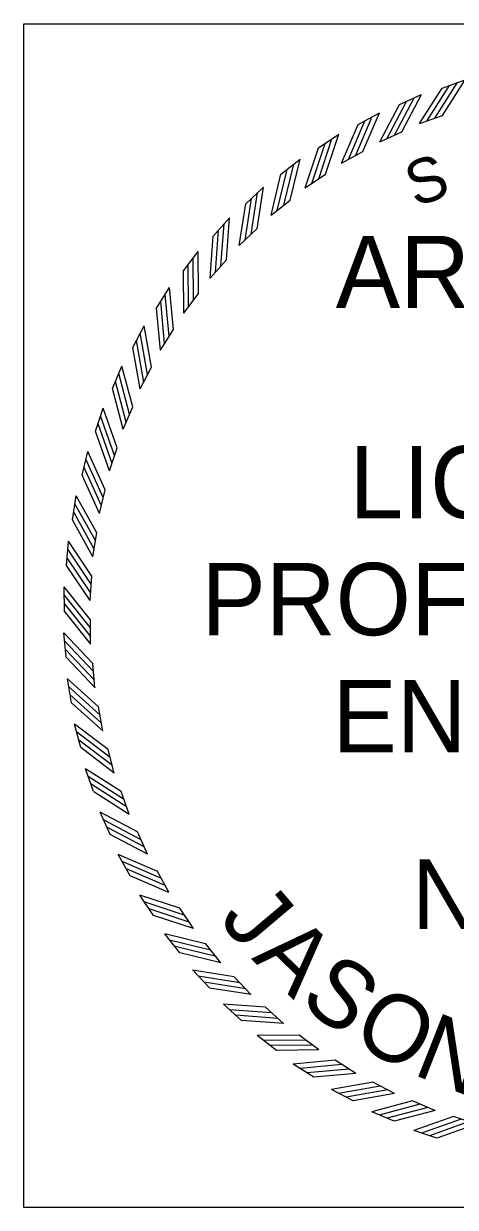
# Model space of a CAD drawing. Extents: x 0 to 1228740, y 0 to 152440.
# Drawn here: x 34.454 to 35.456, y 22.732 to 25.482 of the extents above; entities that cross this region are included whole.
import ezdxf

# ---------------------------------------------------------------- set-up
doc = ezdxf.new("R2010")
doc.units = 0
doc.layers.add('STAMP_JMT', color=7, linetype='Continuous')

msp = doc.modelspace()

# ---------------------------------------------------------------- linework, layer by layer
at = {"layer": 'STAMP_JMT'}
for p, q in [((35.4258, 25.332), (35.4792, 25.3509)), ((35.3263, 25.2938), (35.3779, 25.317)), ((35.2303, 25.2474), (35.2798, 25.2748)), ((35.3732, 25.2496), (35.4266, 25.2684)), ((35.1385, 25.1933), (35.1855, 25.2247)), ((35.2806, 25.2072), (35.3323, 25.2305)), ((35.0514, 25.1318), (35.0957, 25.167)), ((35.1919, 25.1574), (35.2415, 25.1849)), ((35.1077, 25.1005), (35.1548, 25.1319)), ((34.9697, 25.0634), (35.011, 25.1021)), ((35.0284, 25.0367), (35.0728, 25.072)), ((34.894, 24.9884), (34.9319, 25.0303)), ((34.9546, 24.9667), (34.9959, 25.0055)), ((34.8247, 24.9074), (34.859, 24.9523)), ((34.8869, 24.8908), (34.9249, 24.9328)), ((34.7623, 24.821), (34.7928, 24.8686)), ((34.8256, 24.8095), (34.86, 24.8546)), ((34.7072, 24.7297), (34.7337, 24.7796)), ((34.7713, 24.7235), (34.8019, 24.7712)), ((34.6599, 24.6341), (34.6822, 24.6861)), ((34.7243, 24.6333), (34.7508, 24.6834)), ((34.6207, 24.535), (34.6386, 24.5887)), ((34.6849, 24.5395), (34.7072, 24.5916)), ((34.5897, 24.433), (34.6031, 24.488)), ((34.6534, 24.4428), (34.6713, 24.4966)), ((34.63, 24.3438), (34.6434, 24.3989)), ((34.5673, 24.3288), (34.5761, 24.3847)), ((34.6148, 24.2432), (34.6236, 24.2992)), ((34.5536, 24.2231), (34.5578, 24.2795)), ((34.5487, 24.1166), (34.5481, 24.1732)), ((34.608, 24.1417), (34.6121, 24.1982)), ((34.6095, 24.04), (34.609, 24.0967)), ((34.5525, 24.0101), (34.5473, 24.0664)), ((34.6195, 23.9388), (34.6143, 23.9952)), ((34.5652, 23.9042), (34.5554, 23.9599)), ((34.6378, 23.8387), (34.628, 23.8945)), ((34.5865, 23.7998), (34.5721, 23.8545)), ((34.6643, 23.7405), (34.6499, 23.7953)), ((34.6164, 23.6975), (34.5976, 23.7508)), ((34.6989, 23.6448), (34.68, 23.6982)), ((34.6547, 23.598), (34.6315, 23.6495)), ((34.7412, 23.5523), (34.7179, 23.604)), ((34.701, 23.502), (34.6736, 23.5515)), ((34.791, 23.4636), (34.7636, 23.5132)), ((34.7551, 23.4101), (34.7237, 23.4572)), ((34.8479, 23.3793), (34.8165, 23.4264)), ((34.8166, 23.3231), (34.7814, 23.3674)), ((34.9117, 23.3), (34.8765, 23.3444)), ((34.8851, 23.2414), (34.8464, 23.2826)), ((34.9817, 23.2262), (34.943, 23.2676)), ((34.96, 23.1656), (34.9181, 23.2035)), ((35.0576, 23.1585), (35.0156, 23.1965)), ((35.041, 23.0963), (34.9961, 23.1306)), ((35.1389, 23.0973), (35.0938, 23.1317)), ((35.2249, 23.043), (35.1772, 23.0735)), ((35.1275, 23.0339), (35.0798, 23.0644)), ((35.3151, 22.996), (35.265, 23.0225)), ((35.2188, 22.9789), (35.1688, 23.0053)), ((35.4089, 22.9565), (35.3568, 22.9788)), ((35.3143, 22.9316), (35.2623, 22.9538)), ((35.5056, 22.925), (35.4518, 22.9429)), ((35.4134, 22.8923), (35.3597, 22.9102))]:
    msp.add_line(p, q, dxfattribs=at)
msp.add_lwpolyline([(34.454, 25.4817), (37.204, 25.4817), (37.204, 22.7317), (34.454, 22.7317)], close=True, dxfattribs=at)
for points in [[(35.3731, 25.2495), (35.4258, 25.3319)], [(35.3903, 25.2554), (35.443, 25.3378)], [(35.4087, 25.2623), (35.4614, 25.3448)], [(35.4265, 25.2685), (35.4792, 25.3509)], [(35.2973, 25.2145), (35.343, 25.301)], [(35.315, 25.2229), (35.3607, 25.3095)], [(35.3323, 25.2305), (35.3779, 25.317)], [(35.2415, 25.1849), (35.2798, 25.2749)], [(35.2806, 25.2072), (35.3263, 25.2937)], [(35.1919, 25.1574), (35.2303, 25.2474)], [(35.2079, 25.166), (35.2463, 25.256)], [(35.2249, 25.1759), (35.2633, 25.2659)], [(35.1547, 25.1319), (35.1856, 25.2248)], [(35.1076, 25.1004), (35.1385, 25.1933)], [(35.1229, 25.1103), (35.1537, 25.2032)], [(35.139, 25.1216), (35.1698, 25.2145)], [(35.0727, 25.072), (35.0957, 25.1671)], [(35.0427, 25.0478), (35.0658, 25.1429)], [(35.0578, 25.0604), (35.0809, 25.1555)], [(35.0283, 25.0367), (35.0514, 25.1318)], [(34.982, 24.9927), (34.9971, 25.0894)], [(34.9959, 25.0054), (35.011, 25.1021)], [(34.9546, 24.9666), (34.9697, 25.0633)], [(34.968, 24.9789), (34.9831, 25.0756)], [(34.9248, 24.9328), (34.9319, 25.0304)], [(34.8992, 24.9041), (34.9063, 25.0017)], [(34.912, 24.9189), (34.9191, 25.0165)], [(34.8869, 24.8907), (34.894, 24.9883)], [(34.86, 24.8546), (34.859, 24.9524)], [(34.8368, 24.8238), (34.8358, 24.9217)], [(34.8484, 24.8397), (34.8474, 24.9375)], [(34.8256, 24.8094), (34.8247, 24.9073)], [(34.8018, 24.7712), (34.7928, 24.8686)], [(34.7813, 24.7387), (34.7722, 24.8361)], [(34.7915, 24.7554), (34.7825, 24.8529)], [(34.7713, 24.7234), (34.7623, 24.8209)], [(34.7508, 24.6834), (34.7337, 24.7797)], [(34.7418, 24.6668), (34.7247, 24.7631)], [(34.7243, 24.6332), (34.7073, 24.7296)], [(34.733, 24.6492), (34.7159, 24.7456)], [(34.6996, 24.5743), (34.6746, 24.6689)], [(34.7071, 24.5916), (34.6822, 24.6862)], [(34.6923, 24.5561), (34.6673, 24.6507)], [(34.6849, 24.5394), (34.66, 24.634)], [(34.6712, 24.4965), (34.6385, 24.5887)], [(34.6651, 24.4787), (34.6324, 24.5709)], [(34.6534, 24.4427), (34.6207, 24.5349)], [(34.6593, 24.4599), (34.6266, 24.5521)], [(34.6433, 24.3988), (34.6031, 24.488)], [(34.6345, 24.3614), (34.5942, 24.4506)], [(34.6387, 24.3806), (34.5985, 24.4698)], [(34.63, 24.3437), (34.5898, 24.4329)], [(34.6204, 24.2806), (34.573, 24.3661)], [(34.6235, 24.2991), (34.5761, 24.3847)], [(34.6178, 24.2611), (34.5704, 24.3467)], [(34.6148, 24.2431), (34.5674, 24.3287)], [(34.6105, 24.1794), (34.5562, 24.2608)], [(34.6121, 24.1982), (34.5577, 24.2795)], [(34.6095, 24.1598), (34.5552, 24.2411)], [(34.608, 24.1416), (34.5537, 24.223)], [(34.609, 24.0966), (34.5481, 24.1732)], [(34.609, 24.0778), (34.5481, 24.1544)], [(34.6096, 24.0581), (34.5487, 24.1347)], [(34.6096, 24.0399), (34.5487, 24.1165)], [(34.6143, 23.9951), (34.5473, 24.0664)], [(34.6158, 23.9764), (34.5488, 24.0477)], [(34.6181, 23.9568), (34.5511, 24.0281)], [(34.6196, 23.9387), (34.5526, 24.01)], [(34.628, 23.8944), (34.5553, 23.96)], [(34.6311, 23.8759), (34.5584, 23.9414)], [(34.6349, 23.8566), (34.5622, 23.9221)], [(34.6379, 23.8386), (34.5652, 23.9042)], [(34.6499, 23.7952), (34.5721, 23.8545)], [(34.6545, 23.777), (34.5767, 23.8363)], [(34.6599, 23.7581), (34.5821, 23.8174)], [(34.6644, 23.7404), (34.5866, 23.7997)], [(34.68, 23.6981), (34.5975, 23.7508)], [(34.6861, 23.6803), (34.6036, 23.733)], [(34.693, 23.662), (34.6106, 23.7146)], [(34.6989, 23.6447), (34.6165, 23.6974)], [(34.7179, 23.6039), (34.6314, 23.6496)], [(34.7255, 23.5866), (34.639, 23.6323)], [(34.7339, 23.5689), (34.6474, 23.6146)], [(34.7413, 23.5522), (34.6547, 23.5979)], [(34.7635, 23.5131), (34.6735, 23.5515)], [(34.7725, 23.4965), (34.6825, 23.5349)], [(34.7824, 23.4795), (34.6924, 23.5179)], [(34.7911, 23.4635), (34.7011, 23.5019)], [(34.8165, 23.4264), (34.7237, 23.4572)], [(34.8268, 23.4106), (34.734, 23.4414)], [(34.8381, 23.3945), (34.7452, 23.4253)], [(34.848, 23.3793), (34.7552, 23.4101)], [(34.8765, 23.3443), (34.7814, 23.3674)], [(34.888, 23.3295), (34.7929, 23.3525)], [(34.9006, 23.3143), (34.8055, 23.3374)], [(34.9118, 23.3), (34.8167, 23.323)], [(34.943, 23.2675), (34.8463, 23.2826)], [(34.9557, 23.2536), (34.8591, 23.2688)], [(34.9695, 23.2396), (34.8728, 23.2547)], [(34.9818, 23.2262), (34.8851, 23.2413)], [(35.0156, 23.1964), (34.918, 23.2035)], [(35.0295, 23.1837), (34.9319, 23.1908)], [(35.0443, 23.1708), (34.9467, 23.1779)], [(35.0577, 23.1585), (34.9601, 23.1656)], [(35.0939, 23.1316), (34.996, 23.1306)], [(35.1087, 23.12), (35.0109, 23.119)], [(35.1246, 23.1085), (35.0268, 23.1075)], [(35.139, 23.0973), (35.0411, 23.0963)], [(35.1772, 23.0735), (35.0798, 23.0644)], [(35.193, 23.0632), (35.0956, 23.0541)], [(35.2098, 23.0529), (35.1123, 23.0439)], [(35.225, 23.043), (35.1276, 23.0339)], [(35.2651, 23.0224), (35.1687, 23.0053)], [(35.2816, 23.0134), (35.1853, 22.9964)], [(35.2992, 23.0046), (35.2029, 22.9875)], [(35.3152, 22.996), (35.2189, 22.9789)], [(35.3568, 22.9788), (35.2622, 22.9538)], [(35.3741, 22.9712), (35.2795, 22.9462)], [(35.3923, 22.9639), (35.2977, 22.9389)], [(35.409, 22.9566), (35.3144, 22.9316)], [(35.4519, 22.9429), (35.3597, 22.9102)], [(35.4697, 22.9368), (35.3775, 22.904)], [(35.4885, 22.931), (35.3963, 22.8982)], [(35.5057, 22.9251), (35.4135, 22.8923)]]:
    msp.add_lwpolyline(points, dxfattribs=at)

# ---------------------------------------------------------------- texts
for s, height, rotation, p in [('S', 0.1029, 19.7726, (35.3632, 25.0548)), ('J', 0.1562, 310.1419, (34.9045, 23.4003)), ('A', 0.1562, 315.9647, (34.9814, 23.3093)), ('S', 0.1562, 323.2433, (35.0897, 23.2071)), ('O', 0.1562, 330.5218, (35.2101, 23.1196)), ('N', 0.1562, 338.5282, (35.3542, 23.0417))]:
    msp.add_text(s, height=height, rotation=rotation, dxfattribs=at).set_placement(p)
for s, height, p in [('ARKANSAS', 0.16791, (35.1784, 24.8208)), ('LICENSED', 0.16791, (35.2103, 24.3327)), ('PROFESSIONAL', 0.167907, (34.8665, 24.0609)), ('ENGINEER', 0.16791, (35.1704, 23.789)), ('No.21250', 0.16191, (35.3555, 23.378))]:
    msp.add_text(s, height=height, dxfattribs=at).set_placement(p)

doc.saveas('drawing.dxf')
